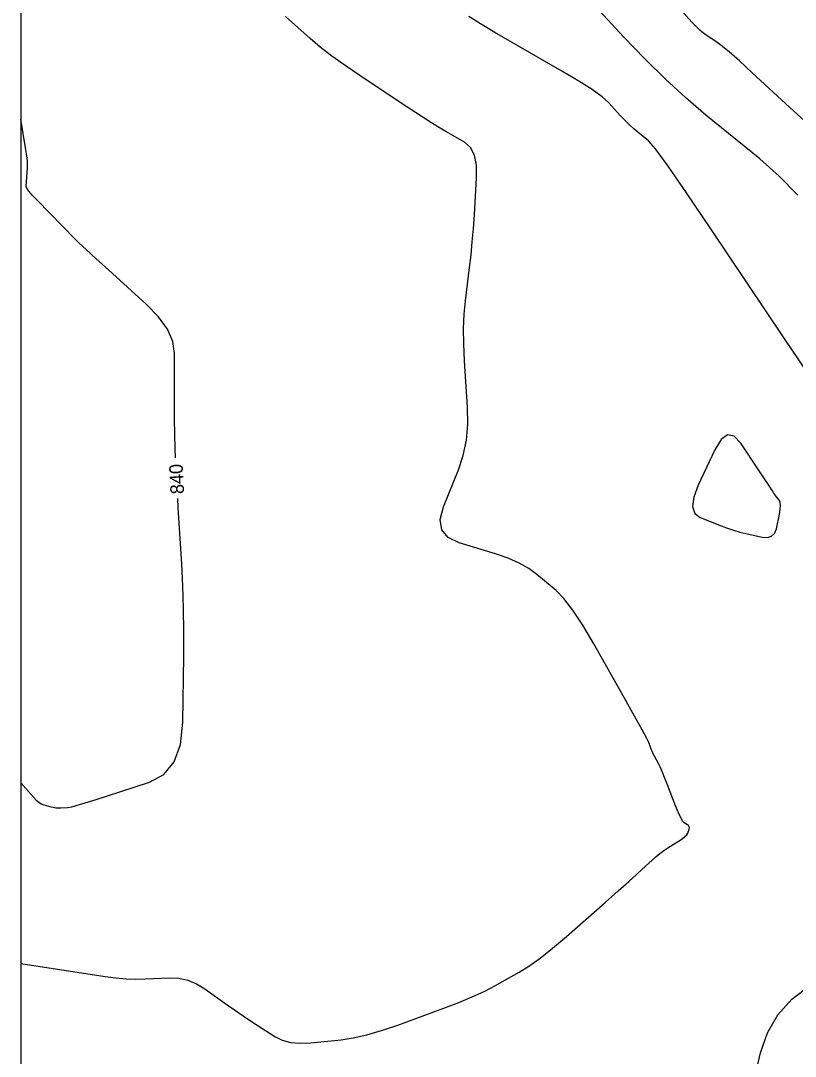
# Model space of a CAD drawing. Extents: x 2082232 to 2083549, y 592624 to 593832.
# Drawn here: x 2082231.8 to 2082271.9, y 593225.9 to 593279.4 of the extents above; entities that cross this region are included whole.
import ezdxf

# ---------------------------------------------------------------- set-up
doc = ezdxf.new("R2010")
doc.units = 0
for name, color, linetype in [('DT_X_Contour_Major', 7, 'Continuous'), ('DT_X_Contour_Minor', 7, 'Continuous'), ('DT_X_TIN_Hull', 7, 'Continuous')]:
    doc.layers.add(name, color=color, linetype=linetype)

msp = doc.modelspace()

# ---------------------------------------------------------------- linework, layer by layer
at = {"layer": 'DT_X_Contour_Major'}
for points in [[(2082239.798, 593256.817), (2082239.782, 593257.297), (2082239.749, 593258.806), (2082239.743, 593259.076), (2082239.739, 593259.242), (2082239.738, 593259.303), (2082239.744, 593262.219), (2082239.654, 593262.839), (2082239.38, 593263.471), (2082238.924, 593264.114), (2082238.286, 593264.767), (2082236.338, 593266.525), (2082235.682, 593267.12), (2082235.173, 593267.585), (2082234.813, 593267.921), (2082234.6, 593268.127), (2082232.631, 593270.141), (2082232.384, 593270.403), (2082232.209, 593270.612), (2082232.106, 593270.766), (2082232.076, 593270.867), (2082232.146, 593271.811), (2082232.147, 593271.966), (2082232.132, 593272.174), (2082232.1, 593272.434), (2082232.052, 593272.746), (2082231.787, 593274.325)], [(2082231.787, 593240.013), (2082232.442, 593239.268), (2082232.582, 593239.124), (2082232.719, 593239.011), (2082232.854, 593238.928), (2082232.987, 593238.877), (2082233.34, 593238.78), (2082233.472, 593238.75), (2082233.603, 593238.729), (2082233.734, 593238.72), (2082233.864, 593238.721), (2082234.211, 593238.738), (2082234.431, 593238.778), (2082234.831, 593238.885), (2082235.412, 593239.06), (2082236.173, 593239.303), (2082238.442, 593240.04), (2082239.188, 593240.441), (2082239.727, 593241.094), (2082240.056, 593241.998), (2082240.177, 593243.152), (2082240.222, 593246.565), (2082240.228, 593247.822), (2082240.213, 593249.034), (2082240.177, 593250.2), (2082240.119, 593251.321), (2082239.937, 593254.249), (2082239.909, 593254.72)]]:
    msp.add_lwpolyline(points, dxfattribs=at)
at = {"layer": 'DT_X_Contour_Minor'}
for points in [[(2082271.987, 593270.407), (2082271.033, 593271.388), (2082270.02, 593272.28), (2082267.24, 593274.538), (2082266.193, 593275.426), (2082265.137, 593276.394), (2082264.071, 593277.444), (2082262.996, 593278.575), (2082260.118, 593281.699)], [(2082231.787, 593230.669), (2082236.151, 593230.001), (2082236.704, 593229.928), (2082237.235, 593229.883), (2082237.744, 593229.864), (2082238.231, 593229.873), (2082239.501, 593229.933), (2082239.971, 593229.914), (2082240.431, 593229.812), (2082240.881, 593229.627), (2082241.319, 593229.359), (2082242.475, 593228.535), (2082242.896, 593228.237), (2082243.295, 593227.961), (2082243.671, 593227.708), (2082244.025, 593227.478), (2082244.936, 593226.893), (2082245.308, 593226.708), (2082245.743, 593226.594), (2082246.239, 593226.549), (2082246.797, 593226.573), (2082248.367, 593226.732), (2082248.991, 593226.824), (2082249.687, 593226.982), (2082250.455, 593227.204), (2082251.295, 593227.492), (2082253.629, 593228.346), (2082254.453, 593228.659), (2082255.177, 593228.958), (2082255.799, 593229.244), (2082256.32, 593229.516), (2082257.574, 593230.222), (2082258.079, 593230.536), (2082258.655, 593230.949), (2082259.301, 593231.461), (2082260.017, 593232.073), (2082262.019, 593233.834), (2082262.701, 593234.435), (2082263.245, 593234.917), (2082263.651, 593235.28), (2082263.92, 593235.525), (2082264.452, 593236.017), (2082264.652, 593236.195), (2082264.855, 593236.36), (2082265.06, 593236.511), (2082265.268, 593236.649), (2082265.824, 593237.001), (2082266.01, 593237.125), (2082266.15, 593237.236), (2082266.245, 593237.333), (2082266.293, 593237.415), (2082266.363, 593237.616), (2082266.378, 593237.687), (2082266.369, 593237.747), (2082266.338, 593237.799), (2082266.284, 593237.84), (2082266.11, 593237.937), (2082266.033, 593238.02), (2082265.934, 593238.196), (2082265.811, 593238.465), (2082265.665, 593238.827), (2082265.246, 593239.916), (2082265.099, 593240.291), (2082264.973, 593240.599), (2082264.867, 593240.84), (2082264.782, 593241.013), (2082264.584, 593241.387), (2082264.515, 593241.521), (2082264.456, 593241.643), (2082264.408, 593241.753), (2082264.37, 593241.85), (2082264.282, 593242.094), (2082264.179, 593242.306), (2082263.934, 593242.759), (2082263.549, 593243.453), (2082263.022, 593244.389), (2082261.429, 593247.206), (2082260.86, 593248.17), (2082260.346, 593248.949), (2082259.889, 593249.543), (2082259.487, 593249.951), (2082258.491, 593250.793), (2082258.077, 593251.096), (2082257.581, 593251.374), (2082257.004, 593251.626), (2082256.345, 593251.852), (2082254.479, 593252.421), (2082253.904, 593252.698), (2082253.576, 593253.101), (2082253.495, 593253.629), (2082253.662, 593254.284), (2082254.437, 593256.198), (2082254.684, 593256.939), (2082254.843, 593257.725), (2082254.916, 593258.557), (2082254.901, 593259.435), (2082254.745, 593261.835), (2082254.704, 593262.704), (2082254.697, 593263.509), (2082254.726, 593264.252), (2082254.79, 593264.931), (2082255.007, 593266.658), (2082255.083, 593267.314), (2082255.15, 593267.987), (2082255.208, 593268.678), (2082255.256, 593269.386), (2082255.371, 593271.296), (2082255.364, 593271.948), (2082255.257, 593272.473), (2082255.049, 593272.871), (2082254.742, 593273.14), (2082253.788, 593273.689), (2082253.375, 593273.936), (2082252.85, 593274.263), (2082252.215, 593274.673), (2082251.469, 593275.163), (2082249.332, 593276.579), (2082248.57, 593277.097), (2082247.889, 593277.589), (2082247.288, 593278.054), (2082246.766, 593278.493), (2082245.483, 593279.629)], [(2082272.501, 593261.196), (2082271.255, 593263.058), (2082267.498, 593268.663), (2082266.239, 593270.523), (2082265.281, 593271.899), (2082264.623, 593272.792), (2082264.266, 593273.202), (2082263.714, 593273.65), (2082263.504, 593273.83), (2082263.285, 593274.031), (2082263.059, 593274.256), (2082262.825, 593274.503), (2082262.191, 593275.191), (2082261.862, 593275.486), (2082261.352, 593275.856), (2082260.66, 593276.299), (2082259.786, 593276.817), (2082257.215, 593278.297), (2082256.322, 593278.815), (2082255.573, 593279.259), (2082254.968, 593279.628)], [(2082272.331, 593274.246), (2082271.572, 593274.935), (2082269.63, 593276.73), (2082268.966, 593277.337), (2082268.432, 593277.808), (2082268.027, 593278.145), (2082267.752, 593278.347), (2082267.192, 593278.708), (2082266.914, 593278.936), (2082266.501, 593279.352), (2082265.952, 593279.956)], [(2082271.036, 593253.91), (2082271.08, 593254.167), (2082271.095, 593254.371), (2082271.082, 593254.521), (2082271.039, 593254.617), (2082270.887, 593254.801), (2082270.835, 593254.865), (2082270.793, 593254.921), (2082270.761, 593254.967), (2082270.738, 593255.004), (2082270.691, 593255.092), (2082270.632, 593255.186), (2082270.491, 593255.4), (2082270.268, 593255.735), (2082269.963, 593256.192), (2082269.038, 593257.571), (2082268.695, 593257.937), (2082268.357, 593258.003), (2082268.025, 593257.768), (2082267.7, 593257.231), (2082266.84, 593255.4), (2082266.604, 593254.781), (2082266.543, 593254.296), (2082266.655, 593253.946), (2082266.942, 593253.731), (2082267.939, 593253.336), (2082268.305, 593253.198), (2082268.655, 593253.079), (2082268.99, 593252.981), (2082269.309, 593252.903), (2082270.139, 593252.72), (2082270.419, 593252.696), (2082270.636, 593252.76), (2082270.789, 593252.912), (2082270.879, 593253.152), (2082271.036, 593253.91)], [(2082269.383, 593223.145), (2082270.064, 593226.058), (2082270.414, 593227.094), (2082270.954, 593228.016), (2082271.682, 593228.825), (2082272.599, 593229.52)]]:
    msp.add_lwpolyline(points, dxfattribs=at)
at = {"layer": 'DT_X_TIN_Hull'}
msp.add_lwpolyline([(2082231.787, 593284.747), (2082231.787, 593279.307), (2082231.787, 593271.096), (2082231.787, 593270.611), (2082231.787, 593270.343), (2082231.787, 593258.897), (2082231.787, 593258.543), (2082231.787, 593255.909), (2082231.787, 593248.502), (2082231.787, 593246.69), (2082231.787, 593240.328), (2082231.787, 593238.866), (2082231.787, 593235.542), (2082231.787, 593231.373), (2082231.787, 593226.881), (2082231.787, 593223.423)], dxfattribs=at)

# ---------------------------------------------------------------- texts
at = {"layer": 'DT_X_Contour_Major'}
msp.add_text('840', height=0.7, rotation=93.0374, dxfattribs=at).set_placement((2082240.242, 593254.958))

doc.saveas('drawing.dxf')
